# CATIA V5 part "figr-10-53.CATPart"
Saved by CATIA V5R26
Part number: Part1
Bounding box of the stored display mesh (mm): x 0 to 100, y -43.492 to 31.468, z -3.623 to 11.497
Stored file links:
  D:\_Deepak\CATIA\CATIA V5-6R2016_Deepak\Resources\Part files\Partfiles\c10_catia_v5_6r2016_prt\figr-10-53.CATPart
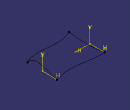
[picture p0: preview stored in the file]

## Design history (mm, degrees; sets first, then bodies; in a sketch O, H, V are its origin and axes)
Set1
  Sketch1 on yz-plane, origin (0, 0, 0), H (0, 1, 0), V (0, 0, 1)
  Plane1: type Offset, RefPlane yz-plane, Offset 100
  Sketch2 on xy-plane, origin (0, 0, 0), H (1, 0, 0), V (0, 1, 0)
    spline S1 through (0, 31.0443) (19.7053, 31.0443) (51.809, 26.4574) (100, 31.0443)
    reference intersected line E1 through (100, 0) direction (0, 1) from Plane1
    point P1 (0, 31.0443)
    point P2 (100, 31.0443)
    coincidence: P1 V, P2 E1
  Sketch3 on xy-plane, origin (0, 0, 0), H (1, 0, 0), V (0, 1, 0)
    spline S1 through (0, -43.492) (26.209, -36.2295) (80.3728, -38.1407) (100, -32.0249)
    reference intersected line E1 through (100, 0) direction (0, 1) from Plane1
    point P1 (0, -43.492)
    point P2 (100, -32.0249)
    coincidence: P1 V, P2 E1
  Sketch4 on Plane1, origin (100, 0, 0), H (0, 1, 0), V (0, 0, 1)
    spline S1 through (-32.0249, 0) (-14.5305, 11.3827) (11.9668, 5.3652) (31.0443, 0)
    reference projected point E1 (31.0443, 0) from vertex of Sketch2
    reference projected point E2 (-32.0249, 0) from vertex of Sketch3
    point P1 (-32.0249, 0)
    point P2 (31.0443, 0)
    coincidence: P1 H, P2 H, P2 E1, P1 E2
  Sketch5 on yz-plane, origin (0, 0, 0), H (0, 1, 0), V (0, 0, 1)
    spline S1 through (31.0443, 0) (7.4727, -3.1675) (-43.492, 0)
    reference projected point E1 (-43.492, 0) from vertex of Sketch3
    reference projected point E2 (31.0443, 0) from vertex of Sketch2
    point P1 (31.0443, 0)
    point P2 (-43.492, 0)
    coincidence: P1 H, P2 H, P2 E1, P1 E2
Body1 (main body)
